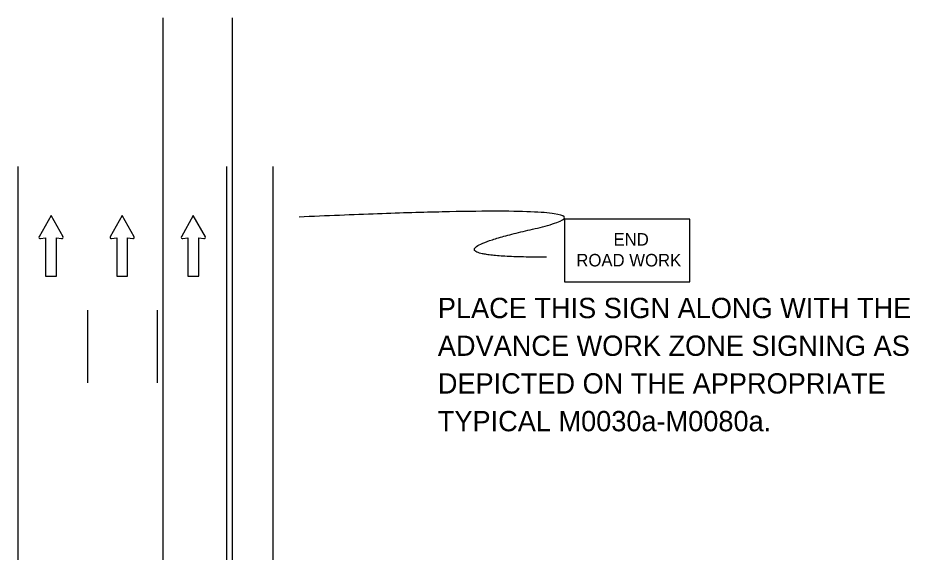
# Model space of a CAD drawing. Extents: x 16782 to 19504, y 6935 to 8243.
# Drawn here: x 17983.1 to 18290.9, y 8050.2 to 8234.5 of the extents above; entities that cross this region are included whole.
import ezdxf

# ---------------------------------------------------------------- set-up
doc = ezdxf.new("R2010")
doc.units = 0
for name, color, linetype in [('ALI_LEGAL_EX', 7, 'Continuous'), ('MT_SCRATCH_LEVEL_E', 7, 'Continuous'), ('PAVT_EDGE_EX', 7, 'Continuous'), ('TRAFFIC_SIGNS_PR', 7, 'Continuous'), ('TYPICAL_TEXT_DIMEN_PR', 7, 'Continuous')]:
    doc.layers.add(name, color=color, linetype=linetype)

msp = doc.modelspace()

# ---------------------------------------------------------------- linework, layer by layer
at = {"layer": 'ALI_LEGAL_EX'}
for p, q in [((18033.11, 8234.45), (18033.11, 7405.27)), ((18057.11, 8234.45), (18057.11, 7405.27)), ((18057.11, 8234.45), (18057.11, 7405.27))]:
    msp.add_line(p, q, dxfattribs=at)
for points in [[(18007.13, 8133.65), (18007.13, 8108.65)], [(18031.13, 8133.65), (18031.13, 8108.65)]]:
    msp.add_lwpolyline(points, dxfattribs=at)
at = {"layer": 'MT_SCRATCH_LEVEL_E'}
for p, q in [((17994.57, 8166.26), (17990.46, 8159.01)), ((17998.71, 8159.01), (17994.57, 8166.26)), ((18019.1, 8166.26), (18014.98, 8159.01)), ((18023.24, 8159.01), (18019.1, 8166.26)), ((18043.65, 8166.26), (18039.54, 8159.01)), ((18047.8, 8159.01), (18043.65, 8166.26)), ((17990.94, 8158.33), (17992.71, 8158.65)), ((17992.71, 8158.65), (17992.71, 8145.39)), ((17996.46, 8145.39), (17996.46, 8158.65)), ((17996.46, 8158.65), (17998.23, 8158.33)), ((18015.47, 8158.33), (18017.24, 8158.65)), ((18017.24, 8158.65), (18017.24, 8145.39)), ((18020.99, 8145.39), (18020.99, 8158.65)), ((18020.99, 8158.65), (18022.76, 8158.33)), ((18040.03, 8158.33), (18041.8, 8158.65)), ((18041.8, 8158.65), (18041.8, 8145.39)), ((18045.54, 8145.39), (18045.54, 8158.65)), ((18045.54, 8158.65), (18047.32, 8158.33)), ((17992.71, 8145.39), (17996.46, 8145.39)), ((18017.24, 8145.39), (18020.99, 8145.39)), ((18041.8, 8145.39), (18045.54, 8145.39))]:
    msp.add_line(p, q, dxfattribs=at)
for centre, start, end in [((17990.86, 8158.79), 150.4248, 279.9638), ((17998.3, 8158.79), 260.0362, 29.7731), ((18015.39, 8158.79), 150.4248, 279.9638), ((18022.83, 8158.79), 260.0362, 29.7731), ((18039.95, 8158.79), 150.4248, 279.9638), ((18047.39, 8158.79), 260.0362, 29.7731)]:
    msp.add_arc(centre, 0.463, start, end, dxfattribs=at)
at = {"layer": 'PAVT_EDGE_EX'}
for p, q in [((17983.13, 8183.26), (17983.13, 7404.46)), ((18055.13, 8183.26), (18055.13, 7404.46)), ((18071.13, 8183.26), (18071.13, 7404.46))]:
    msp.add_line(p, q, dxfattribs=at)
at = {"layer": 'TRAFFIC_SIGNS_PR'}
msp.add_lwpolyline([(18171.71, 8143.41), (18214.91, 8143.41), (18214.91, 8165.01), (18171.71, 8165.01)], close=True, dxfattribs=at)
at = {"layer": 'TYPICAL_TEXT_DIMEN_PR'}
msp.add_open_spline([(18165.45, 8151.93), (18118.22, 8151.93), (18203.24, 8171.28), (18080.14, 8165.78)], degree=2, dxfattribs=at)

# ---------------------------------------------------------------- texts
at = {"layer": 'TRAFFIC_SIGNS_PR'}
for s, height, p in [('END', 4.31, (18188.59, 8155.93)), ('ROAD WORK', 4.31, (18175.77, 8148.75)), ('PLACE THIS SIGN ALONG WITH THE', 7, (18128, 8130.92)), ('ADVANCE WORK ZONE SIGNING AS', 7, (18128, 8117.92)), ('DEPICTED ON THE APPROPRIATE', 7, (18128, 8104.92)), ('TYPICAL M0030a-M0080a.', 7, (18128, 8091.92))]:
    msp.add_text(s, height=height, dxfattribs=at).set_placement(p)

doc.saveas('drawing.dxf')
